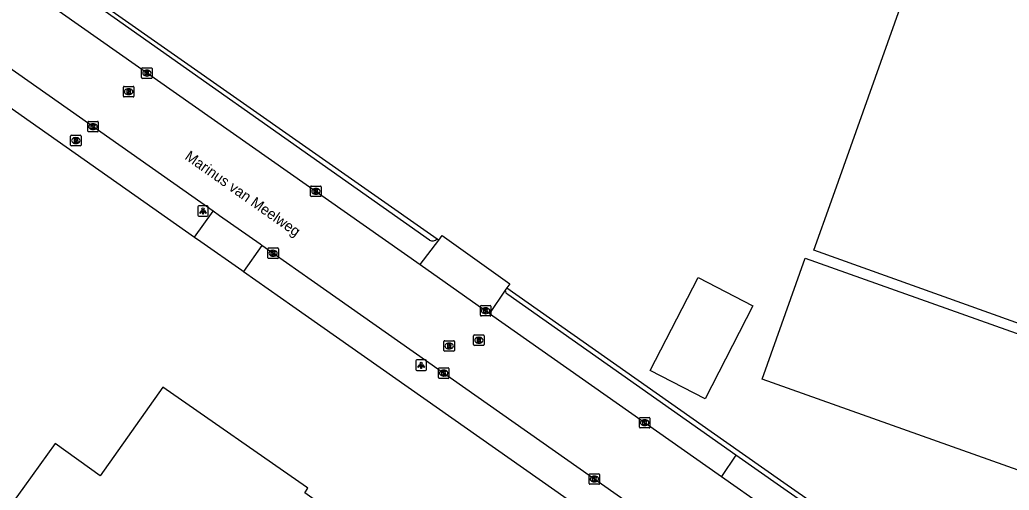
# Model space of a CAD drawing. Extents: x 155018 to 156648, y 383980 to 385733.
# Drawn here: x 155513.9 to 155608.1, y 384927.2 to 384972 of the extents above; entities that cross this region are included whole.
import ezdxf

# ---------------------------------------------------------------- set-up
doc = ezdxf.new("R2010")
doc.units = 0
for name, color, linetype in [('IMGEO_Brandkraan', 7, 'Continuous'), ('IMGEO_Kolk', 7, 'Continuous'), ('IMGEO_Lichtpunt', 7, 'Continuous'), ('IMGEO_Openbare_ruimte_label', 7, 'Continuous'), ('IMGEO_Pand', 7, 'Continuous'), ('IMGEO_Parkeervlak_open', 7, 'Continuous'), ('IMGEO_Rijbaan_lokaal_gesloten', 7, 'Continuous'), ('IMGEO_Rioolput', 7, 'Continuous'), ('IMGEO_Voetpad_open', 7, 'Continuous')]:
    doc.layers.add(name, color=color, linetype=linetype)

msp = doc.modelspace()

# ---------------------------------------------------------------- linework, layer by layer
at = {"layer": 'IMGEO_Brandkraan'}
for p, q in [((155518.761, 384961.012), (155519.613, 384961.012)), ((155518.686, 384960.086), (155518.686, 384960.938)), ((155519.197, 384960.232), (155519.172, 384960.232)), ((155519.174, 384960.792), (155519.199, 384960.792)), ((155519.687, 384960.938), (155519.687, 384960.086)), ((155519.613, 384960.012), (155518.761, 384960.012))]:
    msp.add_line(p, q, dxfattribs=at)
for points in [[(155518.761, 384961.012), (155519.613, 384961.012)], [(155518.686, 384960.086), (155518.686, 384960.938)], [(155519.034, 384960.712), (155519.034, 384960.312), (155519.247, 384960.312)], [(155519.265, 384960.712), (155519.034, 384960.712)], [(155519.213, 384960.631), (155519.159, 384960.631), (155519.159, 384960.555)], [(155519.159, 384960.555), (155519.212, 384960.555)], [(155519.221, 384960.479), (155519.159, 384960.479), (155519.159, 384960.398)], [(155519.159, 384960.398), (155519.221, 384960.398)], [(155519.687, 384960.938), (155519.687, 384960.086)], [(155519.613, 384960.012), (155518.761, 384960.012)]]:
    msp.add_lwpolyline(points, dxfattribs=at)
for centre, radius, start, end in [((155518.763, 384960.936), 0.0765, 91.55205, 178.44795), ((155518.763, 384960.936), 0.0765, 91.55205, 178.44795), ((155519.611, 384960.936), 0.0765, 1.55205, 88.44795), ((155519.611, 384960.936), 0.0765, 1.55205, 88.44795), ((155518.763, 384960.088), 0.0765, 181.55205, 268.44795), ((155518.763, 384960.088), 0.0765, 181.55205, 268.44795), ((155519.214, 384960.593), 0.0379, 267.82845, 90.93552), ((155519.222, 384960.438), 0.0404, 269.87594, 90.50774), ((155519.253, 384960.563), 0.251, 268.66757, 293.53466), ((155519.269, 384960.567), 0.145, 59.4692, 91.53667), ((155519.294, 384960.614), 0.0922, 285.51372, 58.15012), ((155519.299, 384960.422), 0.105, 301.31148, 78.98903), ((155519.611, 384960.088), 0.0765, 271.55205, 358.44795), ((155519.611, 384960.088), 0.0765, 271.55205, 358.44795)]:
    msp.add_arc(centre, radius, start, end, dxfattribs=at)
for centre, major_axis, ratio, start_param, end_param in [((155519.173, 384960.512), (-0.387, 0.002), 0.722429, 4.712389, 7.853982), ((155519.198, 384960.512), (-0.39, 0.002), 0.717154, 1.570796, 4.712389)]:
    msp.add_ellipse(centre, major_axis=major_axis, ratio=ratio, start_param=start_param, end_param=end_param, dxfattribs=at)
at = {"layer": 'IMGEO_Kolk'}
for p, q in [((155525.454, 384966.504), (155525.454, 384967.356)), ((155525.529, 384967.43), (155526.381, 384967.43)), ((155525.965, 384966.65), (155525.94, 384966.65)), ((155525.942, 384967.21), (155525.967, 384967.21)), ((155526.455, 384967.356), (155526.455, 384966.504)), ((155526.381, 384966.43), (155525.529, 384966.43)), ((155520.325, 384961.408), (155520.325, 384962.26)), ((155520.4, 384962.334), (155521.252, 384962.334)), ((155520.813, 384962.114), (155520.838, 384962.114)), ((155521.326, 384962.26), (155521.326, 384961.408)), ((155521.252, 384961.334), (155520.4, 384961.334)), ((155520.836, 384961.554), (155520.811, 384961.554)), ((155541.547, 384955.257), (155541.547, 384956.109)), ((155541.622, 384956.183), (155542.474, 384956.183)), ((155542.058, 384955.403), (155542.033, 384955.403)), ((155542.035, 384955.963), (155542.06, 384955.963)), ((155542.548, 384956.109), (155542.548, 384955.257)), ((155542.474, 384955.183), (155541.622, 384955.183)), ((155537.472, 384949.363), (155537.472, 384950.215)), ((155537.547, 384950.289), (155538.399, 384950.289)), ((155537.96, 384950.069), (155537.985, 384950.069)), ((155538.473, 384950.215), (155538.473, 384949.363)), ((155538.399, 384949.289), (155537.547, 384949.289)), ((155537.983, 384949.509), (155537.958, 384949.509)), ((155557.709, 384943.888), (155557.709, 384944.74)), ((155557.784, 384944.814), (155558.636, 384944.814)), ((155558.22, 384944.034), (155558.195, 384944.034)), ((155558.197, 384944.594), (155558.222, 384944.594)), ((155558.71, 384944.74), (155558.71, 384943.888)), ((155558.636, 384943.814), (155557.784, 384943.814)), ((155553.716, 384937.952), (155553.716, 384938.804)), ((155553.791, 384938.878), (155554.643, 384938.878)), ((155554.204, 384938.658), (155554.229, 384938.658)), ((155554.717, 384938.804), (155554.717, 384937.952)), ((155554.643, 384937.878), (155553.791, 384937.878)), ((155554.227, 384938.098), (155554.202, 384938.098)), ((155572.856, 384933.232), (155572.856, 384934.084)), ((155572.931, 384934.158), (155573.783, 384934.158)), ((155573.344, 384933.938), (155573.369, 384933.938)), ((155573.857, 384934.084), (155573.857, 384933.232)), ((155573.783, 384933.158), (155572.931, 384933.158)), ((155573.367, 384933.378), (155573.342, 384933.378)), ((155568.065, 384927.872), (155568.065, 384928.724)), ((155568.14, 384928.798), (155568.992, 384928.798)), ((155568.576, 384928.018), (155568.551, 384928.018)), ((155568.553, 384928.578), (155568.578, 384928.578)), ((155569.066, 384928.724), (155569.066, 384927.872)), ((155568.992, 384927.798), (155568.14, 384927.798))]:
    msp.add_line(p, q, dxfattribs=at)
for points in [[(155525.454, 384966.504), (155525.454, 384967.356)], [(155525.529, 384967.43), (155526.381, 384967.43)], [(155525.775, 384967.13), (155525.898, 384967.13), (155525.898, 384966.979), (155526.028, 384967.13), (155526.192, 384967.13), (155526.046, 384966.979), (155526.199, 384966.73), (155526.047, 384966.73), (155525.962, 384966.894), (155525.898, 384966.827), (155525.898, 384966.73), (155525.775, 384966.73), (155525.775, 384967.13)], [(155526.455, 384967.356), (155526.455, 384966.504)], [(155526.381, 384966.43), (155525.529, 384966.43)], [(155520.325, 384961.408), (155520.325, 384962.26)], [(155520.4, 384962.334), (155521.252, 384962.334)], [(155520.646, 384962.034), (155520.769, 384962.034), (155520.769, 384961.883), (155520.899, 384962.034), (155521.063, 384962.034), (155520.917, 384961.883), (155521.07, 384961.634), (155520.918, 384961.634), (155520.833, 384961.798), (155520.769, 384961.731), (155520.769, 384961.634), (155520.646, 384961.634), (155520.646, 384962.034)], [(155521.326, 384962.26), (155521.326, 384961.408)], [(155521.252, 384961.334), (155520.4, 384961.334)], [(155541.547, 384955.257), (155541.547, 384956.109)], [(155541.622, 384956.183), (155542.474, 384956.183)], [(155541.868, 384955.883), (155541.991, 384955.883), (155541.991, 384955.732), (155542.121, 384955.883), (155542.285, 384955.883), (155542.139, 384955.732), (155542.292, 384955.483), (155542.14, 384955.483), (155542.055, 384955.647), (155541.991, 384955.58), (155541.991, 384955.483), (155541.868, 384955.483), (155541.868, 384955.883)], [(155542.548, 384956.109), (155542.548, 384955.257)], [(155542.474, 384955.183), (155541.622, 384955.183)], [(155537.472, 384949.363), (155537.472, 384950.215)], [(155537.547, 384950.289), (155538.399, 384950.289)], [(155537.793, 384949.989), (155537.916, 384949.989), (155537.916, 384949.838), (155538.046, 384949.989), (155538.21, 384949.989), (155538.064, 384949.838), (155538.217, 384949.589), (155538.065, 384949.589), (155537.98, 384949.753), (155537.916, 384949.686), (155537.916, 384949.589), (155537.793, 384949.589), (155537.793, 384949.989)], [(155538.473, 384950.215), (155538.473, 384949.363)], [(155538.399, 384949.289), (155537.547, 384949.289)], [(155557.709, 384943.888), (155557.709, 384944.74)], [(155557.784, 384944.814), (155558.636, 384944.814)], [(155558.03, 384944.514), (155558.153, 384944.514), (155558.153, 384944.363), (155558.283, 384944.514), (155558.447, 384944.514), (155558.301, 384944.363), (155558.454, 384944.114), (155558.302, 384944.114), (155558.217, 384944.278), (155558.153, 384944.211), (155558.153, 384944.114), (155558.03, 384944.114), (155558.03, 384944.514)], [(155558.71, 384944.74), (155558.71, 384943.888)], [(155558.636, 384943.814), (155557.784, 384943.814)], [(155553.716, 384937.952), (155553.716, 384938.804)], [(155553.791, 384938.878), (155554.643, 384938.878)], [(155554.037, 384938.578), (155554.16, 384938.578), (155554.16, 384938.427), (155554.29, 384938.578), (155554.454, 384938.578), (155554.308, 384938.427), (155554.461, 384938.178), (155554.309, 384938.178), (155554.224, 384938.342), (155554.16, 384938.275), (155554.16, 384938.178), (155554.037, 384938.178), (155554.037, 384938.578)], [(155554.717, 384938.804), (155554.717, 384937.952)], [(155554.643, 384937.878), (155553.791, 384937.878)], [(155572.856, 384933.232), (155572.856, 384934.084)], [(155572.931, 384934.158), (155573.783, 384934.158)], [(155573.177, 384933.858), (155573.3, 384933.858), (155573.3, 384933.707), (155573.43, 384933.858), (155573.594, 384933.858), (155573.448, 384933.707), (155573.601, 384933.458), (155573.449, 384933.458), (155573.364, 384933.622), (155573.3, 384933.555), (155573.3, 384933.458), (155573.177, 384933.458), (155573.177, 384933.858)], [(155573.857, 384934.084), (155573.857, 384933.232)], [(155573.783, 384933.158), (155572.931, 384933.158)], [(155568.065, 384927.872), (155568.065, 384928.724)], [(155568.14, 384928.798), (155568.992, 384928.798)], [(155568.386, 384928.498), (155568.509, 384928.498), (155568.509, 384928.347), (155568.639, 384928.498), (155568.803, 384928.498), (155568.657, 384928.347), (155568.81, 384928.098), (155568.658, 384928.098), (155568.573, 384928.262), (155568.509, 384928.195), (155568.509, 384928.098), (155568.386, 384928.098), (155568.386, 384928.498)], [(155569.066, 384928.724), (155569.066, 384927.872)], [(155568.992, 384927.798), (155568.14, 384927.798)]]:
    msp.add_lwpolyline(points, dxfattribs=at)
for centre, start, end in [((155525.531, 384967.354), 91.55205, 178.44795), ((155525.531, 384967.354), 91.55205, 178.44795), ((155526.379, 384967.354), 1.55205, 88.44795), ((155526.379, 384967.354), 1.55205, 88.44795), ((155525.531, 384966.506), 181.55205, 268.44795), ((155525.531, 384966.506), 181.55205, 268.44795), ((155526.379, 384966.506), 271.55205, 358.44795), ((155526.379, 384966.506), 271.55205, 358.44795), ((155520.402, 384962.258), 91.55205, 178.44795), ((155520.402, 384962.258), 91.55205, 178.44795), ((155521.25, 384962.258), 1.55205, 88.44795), ((155521.25, 384962.258), 1.55205, 88.44795), ((155520.402, 384961.41), 181.55205, 268.44795), ((155520.402, 384961.41), 181.55205, 268.44795), ((155521.25, 384961.41), 271.55205, 358.44795), ((155521.25, 384961.41), 271.55205, 358.44795), ((155541.624, 384956.107), 91.55205, 178.44795), ((155541.624, 384956.107), 91.55205, 178.44795), ((155542.472, 384956.107), 1.55205, 88.44795), ((155542.472, 384956.107), 1.55205, 88.44795), ((155541.624, 384955.259), 181.55205, 268.44795), ((155541.624, 384955.259), 181.55205, 268.44795), ((155542.472, 384955.259), 271.55205, 358.44795), ((155542.472, 384955.259), 271.55205, 358.44795), ((155537.549, 384950.213), 91.55205, 178.44795), ((155537.549, 384950.213), 91.55205, 178.44795), ((155538.397, 384950.213), 1.55205, 88.44795), ((155538.397, 384950.213), 1.55205, 88.44795), ((155537.549, 384949.365), 181.55205, 268.44795), ((155537.549, 384949.365), 181.55205, 268.44795), ((155538.397, 384949.365), 271.55205, 358.44795), ((155538.397, 384949.365), 271.55205, 358.44795), ((155557.786, 384944.738), 91.55205, 178.44795), ((155557.786, 384944.738), 91.55205, 178.44795), ((155558.634, 384944.738), 1.55205, 88.44795), ((155558.634, 384944.738), 1.55205, 88.44795), ((155557.786, 384943.89), 181.55205, 268.44795), ((155557.786, 384943.89), 181.55205, 268.44795), ((155558.634, 384943.89), 271.55205, 358.44795), ((155558.634, 384943.89), 271.55205, 358.44795), ((155553.793, 384938.802), 91.55205, 178.44795), ((155553.793, 384938.802), 91.55205, 178.44795), ((155554.641, 384938.802), 1.55205, 88.44795), ((155554.641, 384938.802), 1.55205, 88.44795), ((155553.793, 384937.954), 181.55205, 268.44795), ((155553.793, 384937.954), 181.55205, 268.44795), ((155554.641, 384937.954), 271.55205, 358.44795), ((155554.641, 384937.954), 271.55205, 358.44795), ((155572.933, 384934.082), 91.55205, 178.44795), ((155572.933, 384934.082), 91.55205, 178.44795), ((155573.781, 384934.082), 1.55205, 88.44795), ((155573.781, 384934.082), 1.55205, 88.44795), ((155572.933, 384933.234), 181.55205, 268.44795), ((155572.933, 384933.234), 181.55205, 268.44795), ((155573.781, 384933.234), 271.55205, 358.44795), ((155573.781, 384933.234), 271.55205, 358.44795), ((155568.142, 384928.722), 91.55205, 178.44795), ((155568.142, 384928.722), 91.55205, 178.44795), ((155568.99, 384928.722), 1.55205, 88.44795), ((155568.99, 384928.722), 1.55205, 88.44795), ((155568.142, 384927.874), 181.55205, 268.44795), ((155568.142, 384927.874), 181.55205, 268.44795), ((155568.99, 384927.874), 271.55205, 358.44795), ((155568.99, 384927.874), 271.55205, 358.44795)]:
    msp.add_arc(centre, 0.0765, start, end, dxfattribs=at)
for centre, major_axis, ratio, start_param, end_param in [((155525.941, 384966.93), (-0.387, 0.002), 0.722429, 4.712389, 7.853982), ((155525.966, 384966.93), (-0.39, 0.002), 0.717154, 1.570796, 4.712389), ((155520.812, 384961.834), (-0.387, 0.002), 0.722429, 4.712389, 7.853982), ((155520.837, 384961.834), (-0.39, 0.002), 0.717154, 1.570796, 4.712389), ((155542.034, 384955.683), (-0.387, 0.002), 0.722429, 4.712389, 7.853982), ((155542.059, 384955.683), (-0.39, 0.002), 0.717154, 1.570796, 4.712389), ((155537.959, 384949.789), (-0.387, 0.002), 0.722429, 4.712389, 7.853982), ((155537.984, 384949.789), (-0.39, 0.002), 0.717154, 1.570796, 4.712389), ((155558.196, 384944.314), (-0.387, 0.002), 0.722429, 4.712389, 7.853982), ((155558.221, 384944.314), (-0.39, 0.002), 0.717154, 1.570796, 4.712389), ((155554.203, 384938.378), (-0.387, 0.002), 0.722429, 4.712389, 7.853982), ((155554.228, 384938.378), (-0.39, 0.002), 0.717154, 1.570796, 4.712389), ((155573.343, 384933.658), (-0.387, 0.002), 0.722429, 4.712389, 7.853982), ((155573.368, 384933.658), (-0.39, 0.002), 0.717154, 1.570796, 4.712389), ((155568.552, 384928.298), (-0.387, 0.002), 0.722429, 4.712389, 7.853982), ((155568.577, 384928.298), (-0.39, 0.002), 0.717154, 1.570796, 4.712389)]:
    msp.add_ellipse(centre, major_axis=major_axis, ratio=ratio, start_param=start_param, end_param=end_param, dxfattribs=at)
at = {"layer": 'IMGEO_Lichtpunt'}
for p, q in [((155530.799, 384954.205), (155530.799, 384953.398)), ((155530.799, 384954.205), (155530.799, 384953.398)), ((155531.701, 384954.3), (155530.893, 384954.3)), ((155531.701, 384954.3), (155530.893, 384954.3)), ((155531.795, 384953.398), (155531.795, 384954.205)), ((155531.795, 384953.398), (155531.795, 384954.205)), ((155530.893, 384953.304), (155531.701, 384953.304)), ((155530.893, 384953.304), (155531.701, 384953.304)), ((155551.567, 384939.535), (155551.567, 384938.728)), ((155551.567, 384939.535), (155551.567, 384938.728)), ((155552.469, 384939.63), (155551.661, 384939.63)), ((155552.469, 384939.63), (155551.661, 384939.63)), ((155552.563, 384938.728), (155552.563, 384939.535)), ((155552.563, 384938.728), (155552.563, 384939.535)), ((155551.661, 384938.634), (155552.469, 384938.634)), ((155551.661, 384938.634), (155552.469, 384938.634))]:
    msp.add_line(p, q, dxfattribs=at)
for points in [[(155531.173, 384953.869), (155531.212, 384953.841), (155531.024, 384953.579), (155530.986, 384953.606), (155531.173, 384953.869)], [(155531.275, 384953.821), (155531.322, 384953.821), (155531.322, 384953.499), (155531.275, 384953.499), (155531.275, 384953.821)], [(155531.385, 384953.841), (155531.423, 384953.868), (155531.61, 384953.606), (155531.571, 384953.578), (155531.385, 384953.841)], [(155551.941, 384939.199), (155551.98, 384939.171), (155551.792, 384938.909), (155551.754, 384938.936), (155551.941, 384939.199)], [(155552.043, 384939.151), (155552.09, 384939.151), (155552.09, 384938.829), (155552.043, 384938.829), (155552.043, 384939.151)], [(155552.153, 384939.171), (155552.191, 384939.198), (155552.378, 384938.936), (155552.339, 384938.908), (155552.153, 384939.171)]]:
    msp.add_lwpolyline(points, dxfattribs=at)
for centre in [(155531.298, 384954.003), (155552.066, 384939.333)]:
    msp.add_circle(centre, 0.0994, dxfattribs=at)
for centre, start, end in [((155530.893, 384954.205), 90, 180), ((155530.893, 384954.205), 90, 180), ((155531.701, 384954.205), 0, 90), ((155531.701, 384954.205), 0, 90), ((155530.893, 384953.398), 180, 270), ((155530.893, 384953.398), 180, 270), ((155531.701, 384953.398), 270, 0), ((155531.701, 384953.398), 270, 360), ((155551.661, 384939.535), 90, 180), ((155551.661, 384939.535), 90, 180), ((155552.469, 384939.535), 0, 90), ((155552.469, 384939.535), 0, 90), ((155551.661, 384938.728), 180, 270), ((155551.661, 384938.728), 180, 270), ((155552.469, 384938.728), 270, 0), ((155552.469, 384938.728), 270, 360)]:
    msp.add_arc(centre, 0.0946, start, end, dxfattribs=at)
at = {"layer": 'IMGEO_Pand'}
for points in [[(155630.178, 384929.273), (155625.14, 384931.07), (155632.162, 384950.755), (155623.212, 384953.942), (155618.1, 384939.84), (155589.46, 384950.07), (155591.136, 384954.781), (155607.234, 385000), (155633.333, 385073.311), (155662.065, 385063.078), (155658.666, 385053.535), (155667.974, 385050.22)], [(155614.592, 384931.262), (155613.208, 384927.617), (155584.535, 384937.812), (155588.645, 384949.317), (155617.291, 384939.126), (155614.592, 384931.262)], [(155579.102, 384935.924), (155573.878, 384938.612), (155578.46, 384947.479), (155583.664, 384944.79), (155579.102, 384935.924)], [(155541.878, 384926.35), (155540.987, 384926.985), (155541.289, 384927.418), (155541.136, 384927.524), (155527.474, 384937.038), (155521.497, 384928.598), (155517.232, 384931.679), (155514.306, 384927.626), (155500, 384907.81), (155485.234, 384887.357), (155500, 384877.008), (155507.887, 384871.48), (155530.489, 384855.639), (155531.075, 384856.475), (155538.96, 384850.949)]]:
    msp.add_lwpolyline(points, dxfattribs=at)
at = {"layer": 'IMGEO_Parkeervlak_open'}
for points in [[(155553.601, 384951.142), (155553.738, 384951.046)], [(155582.038, 384930.579), (155580.666, 384928.528)]]:
    msp.add_lwpolyline(points, dxfattribs=at)
at = {"layer": 'IMGEO_Rijbaan_lokaal_gesloten'}
for points in [[(155514.115, 384975.3), (155514.295, 384975.174), (155551.965, 384948.699)], [(155532.25, 384953.8), (155512.594, 384967.613), (155508.017, 384970.829)], [(155536.91, 384950.526), (155536.732, 384950.651), (155532.882, 384953.356), (155532.25, 384953.8)], [(155571.894, 384925.942), (155541.6, 384947.23), (155536.91, 384950.526)], [(155551.965, 384948.699), (155558.57, 384944.057)], [(155558.57, 384944.057), (155580.666, 384928.528)], [(155580.666, 384928.528), (155605.603, 384911.034)]]:
    msp.add_lwpolyline(points, dxfattribs=at)
at = {"layer": 'IMGEO_Rioolput'}
for p, q in [((155523.716, 384964.738), (155523.716, 384965.59)), ((155523.791, 384965.664), (155524.643, 384965.664)), ((155524.227, 384964.884), (155524.202, 384964.884)), ((155524.204, 384965.444), (155524.229, 384965.444)), ((155524.717, 384965.59), (155524.717, 384964.738)), ((155524.643, 384964.664), (155523.791, 384964.664)), ((155554.233, 384940.537), (155554.233, 384941.389)), ((155554.308, 384941.463), (155555.16, 384941.463)), ((155554.721, 384941.243), (155554.746, 384941.243)), ((155555.234, 384941.389), (155555.234, 384940.537)), ((155557.067, 384941.086), (155557.067, 384941.938)), ((155557.142, 384942.012), (155557.994, 384942.012)), ((155557.578, 384941.232), (155557.553, 384941.232)), ((155557.555, 384941.792), (155557.58, 384941.792)), ((155558.068, 384941.938), (155558.068, 384941.086)), ((155555.16, 384940.463), (155554.308, 384940.463)), ((155554.744, 384940.683), (155554.719, 384940.683)), ((155557.994, 384941.012), (155557.142, 384941.012))]:
    msp.add_line(p, q, dxfattribs=at)
for points in [[(155523.716, 384964.738), (155523.716, 384965.59)], [(155523.791, 384965.664), (155524.643, 384965.664)], [(155524.305, 384965.362), (155524.053, 384965.364), (155524.053, 384964.964)], [(155524.053, 384964.964), (155524.177, 384964.964), (155524.177, 384965.126), (155524.188, 384965.126)], [(155524.231, 384965.283), (155524.177, 384965.283), (155524.177, 384965.202)], [(155524.177, 384965.202), (155524.229, 384965.202)], [(155524.235, 384965.097), (155524.306, 384964.964), (155524.446, 384964.964), (155524.381, 384965.09)], [(155524.717, 384965.59), (155524.717, 384964.738)], [(155524.643, 384964.664), (155523.791, 384964.664)], [(155554.233, 384940.537), (155554.233, 384941.389)], [(155554.308, 384941.463), (155555.16, 384941.463)], [(155555.234, 384941.389), (155555.234, 384940.537)], [(155557.067, 384941.086), (155557.067, 384941.938)], [(155557.142, 384942.012), (155557.994, 384942.012)], [(155557.656, 384941.71), (155557.404, 384941.712), (155557.404, 384941.312)], [(155557.404, 384941.312), (155557.528, 384941.312), (155557.528, 384941.474), (155557.539, 384941.474)], [(155557.582, 384941.631), (155557.528, 384941.631), (155557.528, 384941.55)], [(155557.528, 384941.55), (155557.58, 384941.55)], [(155557.586, 384941.445), (155557.657, 384941.312), (155557.797, 384941.312), (155557.732, 384941.438)], [(155558.068, 384941.938), (155558.068, 384941.086)], [(155555.16, 384940.463), (155554.308, 384940.463)], [(155554.822, 384941.161), (155554.57, 384941.163), (155554.57, 384940.763)], [(155554.57, 384940.763), (155554.694, 384940.763), (155554.694, 384940.925), (155554.705, 384940.925)], [(155554.748, 384941.082), (155554.694, 384941.082), (155554.694, 384941.001)], [(155554.694, 384941.001), (155554.746, 384941.001)], [(155554.752, 384940.896), (155554.823, 384940.763), (155554.963, 384940.763), (155554.898, 384940.889)], [(155557.994, 384941.012), (155557.142, 384941.012)]]:
    msp.add_lwpolyline(points, dxfattribs=at)
for centre, radius, start, end in [((155523.793, 384965.588), 0.0765, 91.55205, 178.44795), ((155523.793, 384965.588), 0.0765, 91.55205, 178.44795), ((155524.187, 384965.073), 0.0533, 26.02933, 88.69889), ((155524.213, 384965.391), 0.19, 274.7715, 282.96867), ((155524.237, 384965.187), 0.0964, 77.00612, 93.18647), ((155524.251, 384965.244), 0.0378, 276.66336, 79.67722), ((155524.304, 384965.252), 0.109, 350.36119, 89.41601), ((155524.302, 384965.252), 0.112, 277.58423, 350.98172), ((155524.286, 384965.037), 0.108, 29.51342, 73.79051), ((155524.641, 384965.588), 0.0765, 1.55205, 88.44795), ((155524.641, 384965.588), 0.0765, 1.55205, 88.44795), ((155523.793, 384964.74), 0.0765, 181.55205, 268.44795), ((155523.793, 384964.74), 0.0765, 181.55205, 268.44795), ((155524.641, 384964.74), 0.0765, 271.55205, 358.44795), ((155524.641, 384964.74), 0.0765, 271.55205, 358.44795), ((155554.31, 384941.387), 0.0765, 91.55205, 178.44795), ((155554.31, 384941.387), 0.0765, 91.55205, 178.44795), ((155555.158, 384941.387), 0.0765, 1.55205, 88.44795), ((155555.158, 384941.387), 0.0765, 1.55205, 88.44795), ((155557.144, 384941.936), 0.0765, 91.55205, 178.44795), ((155557.144, 384941.936), 0.0765, 91.55205, 178.44795), ((155557.538, 384941.421), 0.0533, 26.02933, 88.69889), ((155557.564, 384941.739), 0.19, 274.7715, 282.96867), ((155557.588, 384941.535), 0.0964, 77.00612, 93.18647), ((155557.602, 384941.592), 0.0378, 276.66336, 79.67722), ((155557.655, 384941.6), 0.109, 350.36119, 89.41601), ((155557.653, 384941.6), 0.112, 277.58423, 350.98172), ((155557.637, 384941.385), 0.108, 29.51342, 73.79051), ((155557.992, 384941.936), 0.0765, 1.55205, 88.44795), ((155557.992, 384941.936), 0.0765, 1.55205, 88.44795), ((155554.31, 384940.539), 0.0765, 181.55205, 268.44795), ((155554.31, 384940.539), 0.0765, 181.55205, 268.44795), ((155554.704, 384940.872), 0.0533, 26.02933, 88.69889), ((155554.73, 384941.19), 0.19, 274.7715, 282.96867), ((155554.754, 384940.986), 0.0964, 77.00612, 93.18647), ((155554.768, 384941.043), 0.0378, 276.66336, 79.67722), ((155554.821, 384941.051), 0.109, 350.36119, 89.41601), ((155554.819, 384941.051), 0.112, 277.58423, 350.98172), ((155554.803, 384940.836), 0.108, 29.51342, 73.79051), ((155555.158, 384940.539), 0.0765, 271.55205, 358.44795), ((155555.158, 384940.539), 0.0765, 271.55205, 358.44795), ((155557.144, 384941.088), 0.0765, 181.55205, 268.44795), ((155557.144, 384941.088), 0.0765, 181.55205, 268.44795), ((155557.992, 384941.088), 0.0765, 271.55205, 358.44795), ((155557.992, 384941.088), 0.0765, 271.55205, 358.44795)]:
    msp.add_arc(centre, radius, start, end, dxfattribs=at)
for centre, major_axis, ratio, start_param, end_param in [((155524.203, 384965.164), (-0.387, 0.002), 0.722429, 4.712389, 7.853982), ((155524.228, 384965.164), (-0.39, 0.002), 0.717154, 1.570796, 4.712389), ((155554.72, 384940.963), (-0.387, 0.002), 0.722429, 4.712389, 7.853982), ((155554.745, 384940.963), (-0.39, 0.002), 0.717154, 1.570796, 4.712389), ((155557.554, 384941.512), (-0.387, 0.002), 0.722429, 4.712389, 7.853982), ((155557.579, 384941.512), (-0.39, 0.002), 0.717154, 1.570796, 4.712389)]:
    msp.add_ellipse(centre, major_axis=major_axis, ratio=ratio, start_param=start_param, end_param=end_param, dxfattribs=at)
at = {"layer": 'IMGEO_Voetpad_open'}
for points in [[(155515.775, 384977.663), (155553.601, 384951.142)], [(155552.875, 384951.036), (155515.938, 384977.083)], [(155506.264, 384968.328), (155510.828, 384965.124), (155530.5, 384951.311)], [(155530.5, 384951.311), (155532.25, 384953.8)], [(155530.5, 384951.311), (155531.101, 384950.889), (155534.984, 384948.163), (155535.161, 384948.038)], [(155551.965, 384948.699), (155553.738, 384951.046)], [(155553.738, 384951.046), (155554.058, 384951.47), (155560.497, 384946.89), (155560.229, 384946.497)], [(155536.91, 384950.526), (155535.161, 384948.038)], [(155535.161, 384948.038), (155539.854, 384944.743), (155570.133, 384923.483)], [(155560.072, 384946.265), (155558.57, 384944.057)], [(155560.229, 384946.497), (155560.072, 384946.265)], [(155560.229, 384946.497), (155580.857, 384931.994), (155586.597, 384927.958), (155607.46, 384913.427)], [(155582.038, 384930.579), (155560.322, 384945.869)], [(155606.786, 384913.278), (155586.27, 384927.599), (155582.038, 384930.579)]]:
    msp.add_lwpolyline(points, dxfattribs=at)
for centre, radius, start, end in [((155553.157, 384951.645), 0.671, 245.15954, 311.45407), ((155560.547, 384946.288), 0.476, 182.79264, 241.73687)]:
    msp.add_arc(centre, radius, start, end, dxfattribs=at)

# ---------------------------------------------------------------- texts
at = {"layer": 'IMGEO_Openbare_ruimte_label'}
msp.add_text('Marinus van Meelweg', height=1, rotation=324.89531, dxfattribs=at).set_placement((155529.487, 384958.798))

doc.saveas('drawing.dxf')
